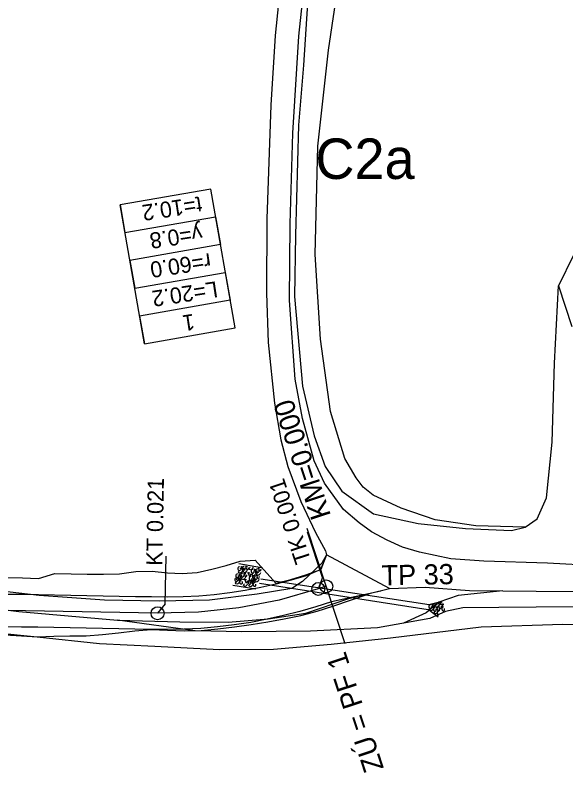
# Model space of a CAD drawing. Extents: x -478000 to -474772, y -1116940 to -1114124.
# Drawn here: x -477296.3 to -477228.2, y -1116631.9 to -1116538.3 of the extents above; entities that cross this region are included whole.
import ezdxf

# ---------------------------------------------------------------- set-up
doc = ezdxf.new("R2010")
doc.units = 0
for name, color, linetype in [('hrana_P', 7, 'Continuous'), ('L', 7, 'Continuous'), ('P', 7, 'Continuous'), ('POLYGONY_SITUACE_PF', 7, 'Continuous'), ('POLYGONY_SITUACE_PF_POPISY', 7, 'Continuous'), ('POLYGONY_SITUACE_PO', 7, 'Continuous'), ('popis', 7, 'Continuous'), ('TABULKY', 7, 'Continuous'), ('TP_HS', 7, 'Continuous')]:
    doc.layers.add(name, color=color, linetype=linetype)

msp = doc.modelspace()

# ---------------------------------------------------------------- linework, layer by layer
for points in [[(-477258.311, -1116607.78), (-477260.157, -1116602.182)], [(-477277.74, -1116611.035), (-477277.633, -1116605.141)], [(-477258.311, -1116607.78), (-477258.822, -1116609.197)], [(-477277.74, -1116611.035), (-477278.69, -1116612.204)]]:
    msp.add_lwpolyline(points)
at = {"layer": 'hrana_P'}
for p, q in [((-477260.984, -1116612.469), (-477258.972, -1116611.925)), ((-477267.124, -1116613.587), (-477265.071, -1116613.267)), ((-477265.071, -1116613.267), (-477263.021, -1116612.908)), ((-477263.021, -1116612.908), (-477260.984, -1116612.469)), ((-477281.496, -1116614.39), (-477279.493, -1116614.22)), ((-477279.493, -1116614.22), (-477277.451, -1116614.304)), ((-477273.304, -1116614.316), (-477271.237, -1116614.131)), ((-477271.237, -1116614.131), (-477269.177, -1116613.887)), ((-477269.177, -1116613.887), (-477267.124, -1116613.587)), ((-477297.507, -1116614.866), (-477295.509, -1116614.987)), ((-477295.509, -1116614.987), (-477293.511, -1116615.092)), ((-477293.511, -1116615.092), (-477291.509, -1116615.045)), ((-477291.509, -1116615.045), (-477289.508, -1116615.007)), ((-477289.508, -1116615.007), (-477287.507, -1116614.969)), ((-477287.507, -1116614.969), (-477285.505, -1116614.824)), ((-477285.505, -1116614.824), (-477283.5, -1116614.605)), ((-477283.5, -1116614.605), (-477281.496, -1116614.39)), ((-477277.451, -1116614.304), (-477275.378, -1116614.355)), ((-477275.378, -1116614.355), (-477273.304, -1116614.316))]:
    msp.add_line(p, q, dxfattribs=at)
for points in [[(-477270.215, -1116606.29), (-477268.462, -1116605.749)], [(-477268.462, -1116605.749), (-477266.637, -1116605.64)], [(-477266.637, -1116605.64), (-477264.08, -1116608.501)], [(-477258.513, -1116606.797), (-477257.817, -1116604.974), (-477258.513, -1116606.797)], [(-477273.799, -1116607.171), (-477271.995, -1116606.764)], [(-477271.995, -1116606.764), (-477270.215, -1116606.29)], [(-477293.381, -1116607.885), (-477291.37, -1116607.303)], [(-477291.37, -1116607.303), (-477289.37, -1116607.348)], [(-477289.37, -1116607.348), (-477287.37, -1116607.355)], [(-477287.37, -1116607.355), (-477285.37, -1116607.361)], [(-477285.37, -1116607.361), (-477283.369, -1116607.327)], [(-477283.369, -1116607.327), (-477281.363, -1116607.036)], [(-477281.363, -1116607.036), (-477279.362, -1116607.004)], [(-477279.362, -1116607.004), (-477277.469, -1116607.185)], [(-477277.469, -1116607.185), (-477275.632, -1116607.299)], [(-477275.632, -1116607.299), (-477273.799, -1116607.171)], [(-477262.205, -1116608.041), (-477260.371, -1116607.442)], [(-477260.328, -1116607.58), (-477262.182, -1116608.125)], [(-477260.371, -1116607.442), (-477258.513, -1116606.797)], [(-477258.513, -1116606.797), (-477260.328, -1116607.58)], [(-477297.379, -1116607.777), (-477295.38, -1116607.831)], [(-477295.38, -1116607.831), (-477293.381, -1116607.885)], [(-477264.054, -1116608.608), (-477265.941, -1116609.028)], [(-477264.08, -1116608.501), (-477262.205, -1116608.041)], [(-477262.182, -1116608.125), (-477264.054, -1116608.608)], [(-477267.841, -1116609.385), (-477269.752, -1116609.679)], [(-477265.941, -1116609.028), (-477267.841, -1116609.385)], [(-477251.093, -1116609.463), (-477257.204, -1116610.769), (-477259.136, -1116611.398)], [(-477295.417, -1116609.902), (-477297.417, -1116609.866)], [(-477293.418, -1116609.938), (-477295.417, -1116609.902)], [(-477291.418, -1116609.974), (-477293.418, -1116609.938)], [(-477289.418, -1116610.01), (-477291.418, -1116609.974)], [(-477287.419, -1116610.046), (-477289.418, -1116610.01)], [(-477285.419, -1116610.082), (-477287.419, -1116610.046)], [(-477283.419, -1116610.118), (-477285.419, -1116610.082)], [(-477281.42, -1116610.154), (-477283.419, -1116610.118)], [(-477279.42, -1116610.19), (-477281.42, -1116610.154)], [(-477277.461, -1116610.213), (-477279.42, -1116610.19)], [(-477275.528, -1116610.176), (-477277.461, -1116610.213)], [(-477273.598, -1116610.075), (-477275.528, -1116610.176)], [(-477271.672, -1116609.909), (-477273.598, -1116610.075)], [(-477269.752, -1116609.679), (-477271.672, -1116609.909)], [(-477258.972, -1116611.925), (-477257.025, -1116611.313), (-477252.531, -1116609.792)], [(-477259.136, -1116611.398), (-477261.119, -1116611.981)], [(-477261.119, -1116611.981), (-477263.12, -1116612.497)], [(-477267.168, -1116613.328), (-477269.21, -1116613.642)], [(-477265.137, -1116612.946), (-477267.168, -1116613.328)], [(-477263.12, -1116612.497), (-477265.137, -1116612.946)], [(-477295.489, -1116613.901), (-477297.489, -1116613.865)], [(-477293.49, -1116613.937), (-477295.489, -1116613.901)], [(-477291.49, -1116613.973), (-477293.49, -1116613.937)], [(-477289.49, -1116614.009), (-477291.49, -1116613.973)], [(-477287.491, -1116614.045), (-477289.49, -1116614.009)], [(-477285.491, -1116614.081), (-477287.491, -1116614.045)], [(-477283.491, -1116614.118), (-477285.491, -1116614.081)], [(-477281.492, -1116614.154), (-477283.491, -1116614.118)], [(-477279.492, -1116614.19), (-477281.492, -1116614.154)], [(-477277.451, -1116614.213), (-477279.492, -1116614.19)], [(-477275.385, -1116614.174), (-477277.451, -1116614.213)], [(-477273.321, -1116614.065), (-477275.385, -1116614.174)], [(-477271.262, -1116613.888), (-477273.321, -1116614.065)], [(-477269.21, -1116613.642), (-477271.262, -1116613.888)]]:
    msp.add_lwpolyline(points, dxfattribs=at)
at = {"layer": 'L'}
for p, q in [((-477227.3, -1116567.963), (-477229.159, -1116571.739)), ((-477229.159, -1116571.739), (-477227.49, -1116576.771)), ((-477301.915, -1116614.261), (-477293.569, -1116615.105)), ((-477293.569, -1116615.105), (-477285.869, -1116615.955)), ((-477285.869, -1116615.955), (-477279.024, -1116616.284)), ((-477264.362, -1116616.623), (-477257.224, -1116616.004)), ((-477257.224, -1116616.004), (-477249.881, -1116615.235)), ((-477279.024, -1116616.284), (-477271.047, -1116616.669)), ((-477271.047, -1116616.669), (-477264.362, -1116616.623))]:
    msp.add_line(p, q, dxfattribs=at)
for points in [[(-477233.279, -1116601.568), (-477239.372, -1116601.418), (-477244.378, -1116600.663), (-477248.6, -1116599.225), (-477252.059, -1116597.605), (-477253.29, -1116596.628), (-477254.151, -1116595.455), (-477255.563, -1116593.08), (-477257.331, -1116587.285), (-477258.559, -1116578.349), (-477259.218, -1116567.863), (-477258.873, -1116554.506), (-477257.563, -1116542.626), (-477255.606, -1116529.592)], [(-477218.373, -1116606.68), (-477230.483, -1116606.006), (-477238.379, -1116605.778), (-477242.437, -1116605.458), (-477246.313, -1116604.647), (-477248.432, -1116604.019), (-477250.309, -1116603.15), (-477252.263, -1116602.153), (-477253.76, -1116601.041), (-477255.715, -1116599.366), (-477258.054, -1116596.141), (-477259.329, -1116593.36), (-477260.782, -1116588.135), (-477261.685, -1116583.286), (-477262.369, -1116573.571), (-477262.313, -1116564.081), (-477261.977, -1116552.873), (-477261.234, -1116540.918), (-477260.089, -1116530.068)], [(-477263.446, -1116534.001), (-477264.173, -1116540.832), (-477264.686, -1116549.435), (-477265.201, -1116563.467), (-477265.243, -1116572.664), (-477265.02, -1116578.756), (-477264.252, -1116586.262), (-477263.438, -1116590.769), (-477262.605, -1116594.049), (-477260.961, -1116598.399), (-477259.165, -1116602.212), (-477257.939, -1116604.474), (-477257.817, -1116604.974), (-477258.388, -1116606.011), (-477260.794, -1116608.277), (-477262.108, -1116609.135), (-477266.366, -1116609.832), (-477272.277, -1116610.564), (-477278.469, -1116610.716), (-477285.242, -1116610.585), (-477293.304, -1116609.991), (-477303.039, -1116608.9)], [(-477260.17, -1116536.865), (-477260.633, -1116544.502), (-477261.285, -1116551.909), (-477261.643, -1116565.479), (-477261.766, -1116573.063), (-477260.756, -1116584.162), (-477259.338, -1116590.261), (-477257.954, -1116594.058), (-477255.906, -1116597.107), (-477251.986, -1116599.903), (-477246.485, -1116601.094), (-477240.65, -1116601.729), (-477234.951, -1116601.956), (-477233.279, -1116601.568)], [(-477415.114, -1116603.397), (-477401.483, -1116606.21), (-477390.32, -1116608.038), (-477380.629, -1116609.538), (-477373.348, -1116610.35), (-477361.864, -1116611.12), (-477352.744, -1116611.253), (-477341.992, -1116611.059), (-477328.24, -1116610.509), (-477321.01, -1116610.283), (-477315.901, -1116610.26), (-477304.626, -1116610.89), (-477295.83, -1116611.965), (-477283.629, -1116613.041), (-477275.914, -1116613.277), (-477269.979, -1116613.304), (-477265.031, -1116612.878), (-477260.374, -1116612.172), (-477255.047, -1116610.365), (-477250.042, -1116609.155), (-477245.607, -1116608.981), (-477240.155, -1116609.387), (-477231.905, -1116609.476), (-477220.847, -1116609.542)], [(-477250.042, -1116609.155), (-477257.817, -1116604.974)], [(-477236.03, -1116609.431), (-477241.555, -1116610.022), (-477243.948, -1116610.809), (-477245.483, -1116612.167), (-477248.283, -1116613.421)], [(-477218.369, -1116611.888), (-477227.284, -1116611.403), (-477236.517, -1116611.488), (-477240.979, -1116611.525), (-477243.115, -1116611.992)], [(-477243.115, -1116611.992), (-477245.054, -1116612.827), (-477251.512, -1116614.016), (-477259.806, -1116614.416), (-477268.259, -1116614.512), (-477274.055, -1116614.372), (-477283.629, -1116613.041)], [(-477249.881, -1116615.235), (-477238.688, -1116613.887), (-477228.602, -1116613.554), (-477218.368, -1116613.797)]]:
    msp.add_lwpolyline(points, dxfattribs=at)
at = {"layer": 'P'}
msp.add_lwpolyline([(-477233.279, -1116601.568), (-477231.782, -1116600.551), (-477230.637, -1116597.929), (-477229.915, -1116591.043), (-477229.617, -1116581.301), (-477229.159, -1116571.739)], dxfattribs=at)
at = {"layer": 'POLYGONY_SITUACE_PF'}
msp.add_lwpolyline([(-477255.482, -1116615.993), (-477257.83, -1116608.87), (-477260.178, -1116601.747)], dxfattribs=at)
at = {"layer": 'POLYGONY_SITUACE_PO'}
msp.add_lwpolyline([(-477257.83, -1116608.87), (-477258.822, -1116609.197), (-477263.677, -1116610.574), (-477268.629, -1116611.538), (-477273.646, -1116612.083), (-477278.69, -1116612.204), (-477350.936, -1116610.9), (-477374.116, -1116609.583), (-477397.125, -1116606.478), (-477419.825, -1116601.602), (-477442.079, -1116594.986), (-477463.756, -1116586.668), (-477497.326, -1116572.273), (-477500.708, -1116571.338), (-477504.217, -1116571.342)], dxfattribs=at)
for centre in [(-477258.822, -1116609.197), (-477257.83, -1116608.87), (-477278.69, -1116612.204)]:
    msp.add_circle(centre, 0.8, dxfattribs=at)
at = {"layer": 'TABULKY'}
msp.add_lwpolyline([(-477280.309, -1116578.905), (-477283.309, -1116561.742), (-477282.71, -1116565.172), (-477271.515, -1116563.214), (-477270.913, -1116566.659), (-477282.107, -1116568.617), (-477281.508, -1116572.046), (-477270.313, -1116570.089), (-477269.713, -1116573.519), (-477280.908, -1116575.476), (-477280.309, -1116578.905), (-477269.114, -1116576.948), (-477272.113, -1116559.793), (-477283.309, -1116561.742)], dxfattribs=at)
at = {"layer": 'TP_HS'}
for p, q in [((-477268.636, -1116606.067), (-477265.822, -1116606.545)), ((-477266.093, -1116608.477), (-477245.26, -1116611.745)), ((-477265.921, -1116607.929), (-477245.138, -1116611.098)), ((-477269.378, -1116608.714), (-477266.559, -1116609.163)), ((-477245.146, -1116611.111), (-477243.499, -1116610.726)), ((-477245.255, -1116611.701), (-477243.999, -1116612.626))]:
    msp.add_line(p, q, dxfattribs=at)
for points in [[(-477268.544, -1116606.46), (-477268.716, -1116606.528), (-477268.775, -1116606.733), (-477268.635, -1116606.912), (-477268.433, -1116606.847), (-477268.436, -1116606.644)], [(-477268.162, -1116606.518), (-477268.388, -1116606.468), (-477268.292, -1116606.692), (-477268.233, -1116606.842), (-477268.039, -1116606.775), (-477268.051, -1116606.629)], [(-477267.971, -1116606.409), (-477268.143, -1116606.476), (-477268.201, -1116606.681), (-477268.061, -1116606.86), (-477267.86, -1116606.795), (-477267.863, -1116606.592)], [(-477267.588, -1116606.466), (-477267.814, -1116606.416), (-477267.718, -1116606.64), (-477267.659, -1116606.79), (-477267.465, -1116606.723), (-477267.477, -1116606.578)], [(-477266.88, -1116606.506), (-477266.984, -1116606.694), (-477267.219, -1116606.828), (-477267.384, -1116606.682), (-477267.241, -1116606.519)], [(-477266.888, -1116606.777), (-477267.06, -1116606.845), (-477267.119, -1116607.049), (-477266.979, -1116607.229), (-477266.777, -1116607.164), (-477266.78, -1116606.961)], [(-477266.506, -1116606.834), (-477266.732, -1116606.784), (-477266.636, -1116607.009), (-477266.577, -1116607.158), (-477266.383, -1116607.091), (-477266.394, -1116606.946)], [(-477266.315, -1116606.725), (-477266.487, -1116606.793), (-477266.545, -1116606.998), (-477266.405, -1116607.177), (-477266.204, -1116607.112), (-477266.207, -1116606.909)], [(-477266.034, -1116606.629), (-477266.26, -1116606.579), (-477266.164, -1116606.803), (-477266.105, -1116606.953), (-477265.911, -1116606.886), (-477265.923, -1116606.74)], [(-477268.799, -1116607.349), (-477268.971, -1116607.417), (-477269.03, -1116607.622), (-477268.889, -1116607.801), (-477268.688, -1116607.736), (-477268.691, -1116607.533)], [(-477268.186, -1116606.921), (-477268.29, -1116607.108), (-477268.525, -1116607.242), (-477268.69, -1116607.096), (-477268.547, -1116606.934)], [(-477268.416, -1116607.406), (-477268.643, -1116607.357), (-477268.547, -1116607.581), (-477268.487, -1116607.731), (-477268.294, -1116607.664), (-477268.305, -1116607.518)], [(-477268.167, -1116607.263), (-477268.339, -1116607.331), (-477268.398, -1116607.536), (-477268.257, -1116607.715), (-477268.056, -1116607.65), (-477268.059, -1116607.447)], [(-477267.809, -1116607.723), (-477267.913, -1116607.911), (-477268.147, -1116608.045), (-477268.313, -1116607.899), (-477268.169, -1116607.737)], [(-477267.612, -1116606.869), (-477267.717, -1116607.056), (-477267.951, -1116607.19), (-477268.116, -1116607.045), (-477267.973, -1116606.882)], [(-477267.785, -1116607.321), (-477268.011, -1116607.271), (-477267.915, -1116607.495), (-477267.856, -1116607.645), (-477267.662, -1116607.578), (-477267.673, -1116607.432)], [(-477267.291, -1116607.234), (-477267.517, -1116607.184), (-477267.421, -1116607.409), (-477267.362, -1116607.558), (-477267.168, -1116607.492), (-477267.179, -1116607.346)], [(-477267.143, -1116607.666), (-477267.315, -1116607.734), (-477267.373, -1116607.938), (-477267.233, -1116608.118), (-477267.032, -1116608.053), (-477267.035, -1116607.85)], [(-477266.53, -1116607.237), (-477266.634, -1116607.425), (-477266.868, -1116607.559), (-477267.034, -1116607.413), (-477266.89, -1116607.25)], [(-477266.76, -1116607.723), (-477266.986, -1116607.673), (-477266.89, -1116607.897), (-477266.831, -1116608.047), (-477266.637, -1116607.98), (-477266.649, -1116607.835)], [(-477266.511, -1116607.58), (-477266.683, -1116607.648), (-477266.742, -1116607.852), (-477266.601, -1116608.032), (-477266.4, -1116607.967), (-477266.403, -1116607.764)], [(-477266.234, -1116607.546), (-477266.46, -1116607.496), (-477266.364, -1116607.721), (-477266.305, -1116607.87), (-477266.111, -1116607.803), (-477266.123, -1116607.658)], [(-477265.956, -1116607.185), (-477266.061, -1116607.373), (-477266.295, -1116607.507), (-477266.46, -1116607.361), (-477266.317, -1116607.198)], [(-477268.92, -1116607.827), (-477269.092, -1116607.895), (-477269.151, -1116608.1), (-477269.011, -1116608.279), (-477268.809, -1116608.214), (-477268.812, -1116608.011)], [(-477268.562, -1116608.288), (-477268.666, -1116608.475), (-477268.901, -1116608.609), (-477269.066, -1116608.463), (-477268.923, -1116608.301)], [(-477268.44, -1116607.809), (-477268.545, -1116607.997), (-477268.779, -1116608.131), (-477268.945, -1116607.985), (-477268.801, -1116607.823)], [(-477268.538, -1116607.885), (-477268.764, -1116607.835), (-477268.668, -1116608.059), (-477268.609, -1116608.209), (-477268.415, -1116608.142), (-477268.427, -1116607.996)], [(-477268.319, -1116608.1), (-477268.491, -1116608.168), (-477268.549, -1116608.372), (-477268.409, -1116608.552), (-477268.208, -1116608.487), (-477268.211, -1116608.284)], [(-477267.566, -1116608.558), (-477267.67, -1116608.745), (-477267.905, -1116608.879), (-477268.07, -1116608.734), (-477267.927, -1116608.571)], [(-477267.707, -1116608.063), (-477267.934, -1116608.013), (-477267.838, -1116608.237), (-477267.779, -1116608.387), (-477267.585, -1116608.32), (-477267.596, -1116608.174)], [(-477267.264, -1116608.144), (-477267.436, -1116608.212), (-477267.495, -1116608.416), (-477267.355, -1116608.596), (-477267.153, -1116608.531), (-477267.156, -1116608.328)], [(-477266.906, -1116608.604), (-477267.01, -1116608.792), (-477267.245, -1116608.926), (-477267.41, -1116608.78), (-477267.267, -1116608.617)], [(-477266.784, -1116608.126), (-477266.889, -1116608.314), (-477267.123, -1116608.447), (-477267.288, -1116608.302), (-477267.145, -1116608.139)], [(-477266.882, -1116608.201), (-477267.108, -1116608.151), (-477267.012, -1116608.376), (-477266.953, -1116608.525), (-477266.759, -1116608.459), (-477266.771, -1116608.313)], [(-477266.663, -1116608.417), (-477266.835, -1116608.485), (-477266.893, -1116608.689), (-477266.753, -1116608.868), (-477266.552, -1116608.803), (-477266.555, -1116608.6)], [(-477266.152, -1116608.04), (-477266.257, -1116608.228), (-477266.491, -1116608.361), (-477266.657, -1116608.216), (-477266.513, -1116608.053)], [(-477244.925, -1116611.124), (-477245.097, -1116611.192), (-477245.156, -1116611.397), (-477245.015, -1116611.576), (-477244.814, -1116611.511), (-477244.817, -1116611.308)], [(-477244.542, -1116611.182), (-477244.769, -1116611.132), (-477244.673, -1116611.356), (-477244.614, -1116611.506), (-477244.42, -1116611.439), (-477244.431, -1116611.294)], [(-477244.477, -1116610.955), (-477244.471, -1116610.971), (-477244.465, -1116610.986), (-477244.452, -1116611.017), (-477244.42, -1116611.072), (-477244.383, -1116611.112), (-477244.361, -1116611.125), (-477244.35, -1116611.128), (-477244.344, -1116611.13), (-477244.341, -1116611.13), (-477244.338, -1116611.131), (-477244.312, -1116611.133), (-477244.281, -1116611.133), (-477244.214, -1116611.127), (-477244.159, -1116611.107), (-477244.142, -1116611.089), (-477244.138, -1116611.078), (-477244.137, -1116611.072), (-477244.136, -1116611.066), (-477244.139, -1116610.863)], [(-477243.889, -1116611.139), (-477243.994, -1116611.327), (-477244.228, -1116611.461), (-477244.393, -1116611.315), (-477244.25, -1116611.152)], [(-477243.997, -1116611.534), (-477244.223, -1116611.484), (-477244.127, -1116611.708), (-477244.068, -1116611.858), (-477243.874, -1116611.791), (-477243.885, -1116611.646)], [(-477244.029, -1116610.85), (-477244.018, -1116610.867), (-477244.009, -1116610.883), (-477244.001, -1116610.897), (-477243.998, -1116610.904), (-477243.995, -1116610.911), (-477243.981, -1116610.948), (-477243.966, -1116610.987), (-477243.952, -1116611.025), (-477243.944, -1116611.043), (-477243.94, -1116611.052), (-477243.938, -1116611.056), (-477243.936, -1116611.06), (-477243.933, -1116611.065), (-477243.929, -1116611.07), (-477243.92, -1116611.077), (-477243.893, -1116611.083), (-477243.827, -1116611.074), (-477243.766, -1116611.041), (-477243.748, -1116611.018), (-477243.743, -1116611.006), (-477243.742, -1116611), (-477243.742, -1116610.993), (-477243.754, -1116610.848)], [(-477243.71, -1116611.138), (-477243.882, -1116611.206), (-477243.941, -1116611.41), (-477243.801, -1116611.589), (-477243.599, -1116611.525), (-477243.602, -1116611.322)], [(-477243.376, -1116611.051), (-477243.396, -1116611.062), (-477243.416, -1116611.073), (-477243.458, -1116611.09), (-477243.499, -1116611.103), (-477243.518, -1116611.108), (-477243.528, -1116611.111), (-477243.537, -1116611.113), (-477243.543, -1116611.114), (-477243.596, -1116611.104), (-477243.661, -1116611.066), (-477243.705, -1116611.015), (-477243.711, -1116610.99), (-477243.709, -1116610.978), (-477243.706, -1116610.973), (-477243.702, -1116610.967), (-477243.559, -1116610.805)], [(-477243.684, -1116610.77), (-477243.675, -1116610.775), (-477243.666, -1116610.778), (-477243.657, -1116610.781), (-477243.652, -1116610.782), (-477243.647, -1116610.783), (-477243.621, -1116610.785), (-477243.613, -1116610.785), (-477243.605, -1116610.786), (-477243.598, -1116610.786), (-477243.59, -1116610.786), (-477243.573, -1116610.785), (-477243.556, -1116610.784), (-477243.54, -1116610.782), (-477243.531, -1116610.781), (-477243.523, -1116610.779), (-477243.506, -1116610.776)], [(-477243.344, -1116611.434), (-477243.516, -1116611.502), (-477243.575, -1116611.706), (-477243.434, -1116611.885), (-477243.233, -1116611.82), (-477243.236, -1116611.618)], [(-477243.328, -1116611.195), (-477243.554, -1116611.145), (-477243.561, -1116611.144), (-477243.566, -1116611.144), (-477243.574, -1116611.147), (-477243.577, -1116611.162), (-477243.547, -1116611.223), (-477243.497, -1116611.3), (-477243.465, -1116611.354), (-477243.461, -1116611.362), (-477243.458, -1116611.369), (-477243.447, -1116611.397), (-477243.437, -1116611.425)], [(-477244.566, -1116611.585), (-477244.671, -1116611.772), (-477244.905, -1116611.906), (-477245.071, -1116611.761), (-477244.927, -1116611.598)], [(-477244.379, -1116611.476), (-477244.551, -1116611.544), (-477244.61, -1116611.749), (-477244.47, -1116611.928), (-477244.268, -1116611.863), (-477244.271, -1116611.66)], [(-477244.021, -1116611.937), (-477244.125, -1116612.124), (-477244.359, -1116612.258), (-477244.525, -1116612.113), (-477244.381, -1116611.95)], [(-477243.897, -1116611.901), (-477244.069, -1116611.969), (-477244.075, -1116611.971), (-477244.081, -1116611.975), (-477244.091, -1116611.982), (-477244.11, -1116612.001), (-477244.133, -1116612.051), (-477244.139, -1116612.111), (-477244.136, -1116612.143), (-477244.132, -1116612.158), (-477244.13, -1116612.166), (-477244.128, -1116612.173), (-477244.116, -1116612.205), (-477244.102, -1116612.236), (-477244.071, -1116612.292), (-477244.033, -1116612.334), (-477244.011, -1116612.346), (-477243.999, -1116612.35), (-477243.987, -1116612.353), (-477243.973, -1116612.354), (-477243.957, -1116612.355)], [(-477243.817, -1116611.871), (-477243.824, -1116611.865), (-477243.831, -1116611.859), (-477243.843, -1116611.847), (-477243.86, -1116611.821), (-477243.865, -1116611.796), (-477243.863, -1116611.785), (-477243.86, -1116611.779), (-477243.856, -1116611.774), (-477243.713, -1116611.611)], [(-477244.03, -1116612.608), (-477244.038, -1116612.599), (-477244.044, -1116612.59), (-477244.046, -1116612.585), (-477244.048, -1116612.581), (-477244.05, -1116612.576), (-477244.051, -1116612.571), (-477244.052, -1116612.566), (-477244.052, -1116612.562), (-477244.052, -1116612.557), (-477244.051, -1116612.553), (-477244.05, -1116612.549), (-477244.048, -1116612.545), (-477244.046, -1116612.541), (-477244.043, -1116612.537), (-477243.994, -1116612.481)]]:
    msp.add_spline(points, degree=3, dxfattribs=at)

# ---------------------------------------------------------------- texts
for s, height, rotation, p in [('t=10.2', 1.9765, 188.60568, (-477273.378, -1116560.671)), ('y=0.8', 1.9765, 188.60568, (-477273.311, -1116564.259)), ('r=60.0', 1.9765, 188.60568, (-477272.238, -1116567.695)), ('L=20.2', 1.9765, 188.60568, (-477271.42, -1116571.169)), ('1', 1.976, 188.60568, (-477274.255, -1116575.196)), ('TK 0.001', 2, 108.2451, (-477259.699, -1116605.7)), ('KT 0.021', 2, 88.96625, (-477278.09, -1116606.342))]:
    msp.add_text(s, height=height, rotation=rotation).set_placement(p)
at = {"layer": 'POLYGONY_SITUACE_PF_POPISY'}
for s, p in [('KM=0.000', (-477257.239, -1116600.126)), ('ZÚ = PF 1', (-477250.698, -1116631.347))]:
    msp.add_text(s, height=2.5, rotation=108.2451, dxfattribs=at).set_placement(p)
at = {"layer": 'popis'}
for s, height, rotation, p in [('C2a', 5, 359.99999, (-477259.184, -1116558.543)), ('TP 33', 2.5, 1.14854, (-477250.979, -1116608.773))]:
    msp.add_text(s, height=height, rotation=rotation, dxfattribs=at).set_placement(p)

doc.saveas('drawing.dxf')
